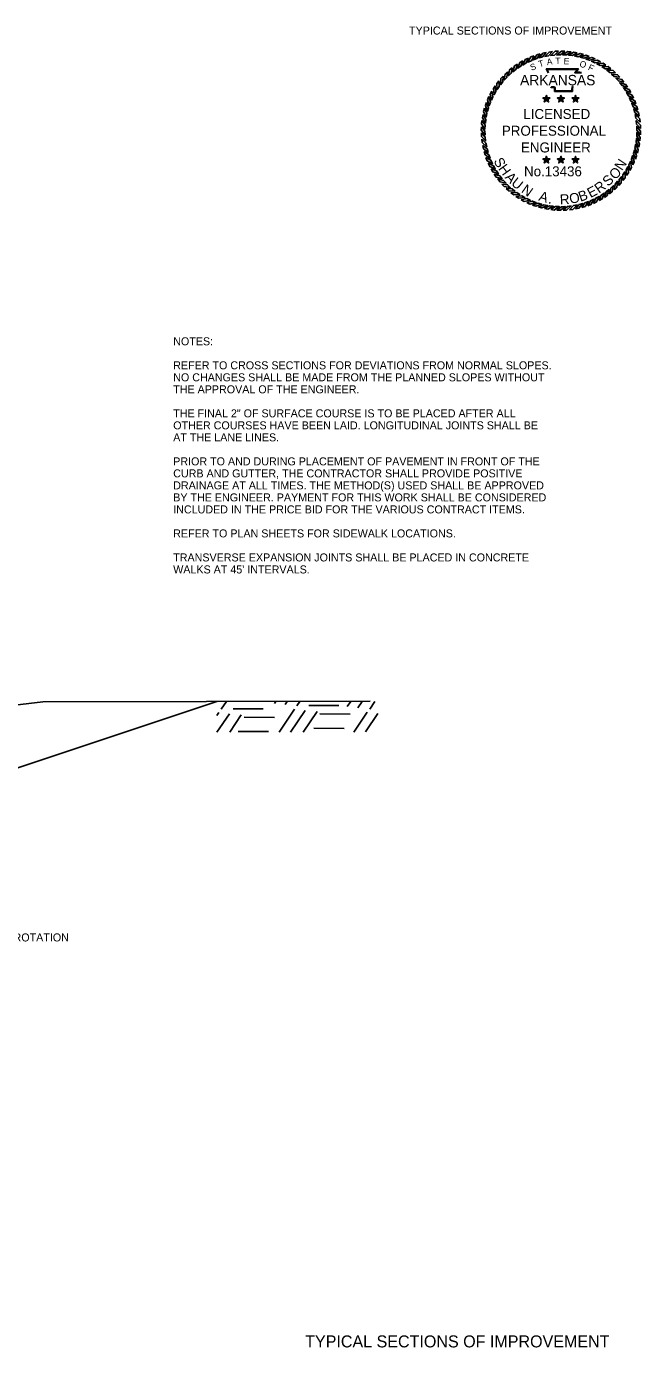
# Model space of a CAD drawing. Extents: x 1001270 to 1003428, y 1840152 to 1842912.
# Drawn here: x 1001382.5 to 1001428.5, y 1842659.1 to 1842758.1 of the extents above; entities that cross this region are included whole.
import ezdxf

# ---------------------------------------------------------------- set-up
doc = ezdxf.new("R2010")
doc.units = 0
for name, color, linetype in [('1', 7, 'Continuous'), ('19', 7, 'Continuous'), ('60', 7, 'Continuous'), ('G-ANNO-SYMB', 7, 'Continuous')]:
    doc.layers.add(name, color=color, linetype=linetype)

msp = doc.modelspace()

# ---------------------------------------------------------------- linework, layer by layer
at = {"layer": '19'}
for p, q in [((1001374.66, 1842700.132), (1001396.746, 1842707.494)), ((1001397.064, 1842706.913), (1001397.455, 1842707.495)), ((1001397.952, 1842706.952), (1001400.212, 1842706.93)), ((1001401.049, 1842707.347), (1001401.155, 1842707.497)), ((1001401.401, 1842705.2), (1001402.553, 1842706.921)), ((1001401.844, 1842707.255), (1001402.01, 1842707.499)), ((1001402.256, 1842705.202), (1001403.348, 1842706.829)), ((1001402.739, 1842707.163), (1001402.965, 1842707.502)), ((1001403.627, 1842707.192), (1001405.888, 1842707.181)), ((1001406.503, 1842707.107), (1001406.765, 1842707.502)), ((1001407.298, 1842707.015), (1001407.63, 1842707.504)), ((1001408.193, 1842706.923), (1001408.574, 1842707.497)), ((1001396.724, 1842706.445), (1001396.878, 1842706.67)), ((1001396.746, 1842705.196), (1001397.673, 1842706.578)), ((1001397.702, 1842705.198), (1001398.568, 1842706.486)), ((1001398.792, 1842706.322), (1001401.052, 1842706.301)), ((1001403.211, 1842705.204), (1001404.243, 1842706.737)), ((1001404.457, 1842706.564), (1001406.728, 1842706.551)), ((1001407.011, 1842705.205), (1001408.008, 1842706.681)), ((1001407.866, 1842705.208), (1001408.802, 1842706.589)), ((1001398.34, 1842705.243), (1001400.61, 1842705.231)), ((1001404.015, 1842705.493), (1001406.275, 1842705.472))]:
    msp.add_line(p, q, dxfattribs=at)
for points in [[(1001303.53, 1842696.307), (1001314.536, 1842695.921), (1001319.13, 1842696.006), (1001322.097, 1842696.031), (1001329.443, 1842696.396), (1001339.767, 1842697.462), (1001355.933, 1842698.662), (1001361.755, 1842701.104), (1001365.939, 1842701.981), (1001371.785, 1842704.915), (1001376.097, 1842706.564), (1001383.698, 1842707.466)], [(1001383.698, 1842707.466), (1001408.216, 1842707.519)]]:
    msp.add_lwpolyline(points, dxfattribs=at)
at = {"layer": 'G-ANNO-SYMB'}
for points in [[(1001419.658, 1842755.512), (1001419.436, 1842755.385), (1001419.276, 1842754.956), (1001419.507, 1842755.108)], [(1001420.078, 1842755.72), (1001419.846, 1842755.611), (1001419.653, 1842755.196), (1001419.896, 1842755.33)], [(1001420.513, 1842755.895), (1001420.273, 1842755.804), (1001420.048, 1842755.406), (1001420.3, 1842755.52)], [(1001420.96, 1842756.035), (1001420.714, 1842755.963), (1001420.458, 1842755.584), (1001420.719, 1842755.678)], [(1001421.416, 1842756.14), (1001421.165, 1842756.087), (1001420.881, 1842755.729), (1001421.148, 1842755.802)], [(1001421.88, 1842756.208), (1001421.625, 1842756.175), (1001421.314, 1842755.841), (1001421.586, 1842755.893)], [(1001422.347, 1842756.24), (1001422.091, 1842756.227), (1001421.754, 1842755.918), (1001422.029, 1842755.948)], [(1001422.816, 1842756.235), (1001422.559, 1842756.242), (1001422.199, 1842755.96), (1001422.476, 1842755.969)], [(1001423.282, 1842756.193), (1001423.027, 1842756.22), (1001422.646, 1842755.968), (1001422.923, 1842755.955)], [(1001423.744, 1842756.115), (1001423.492, 1842756.162), (1001423.092, 1842755.94), (1001423.367, 1842755.906)], [(1001424.198, 1842756), (1001423.951, 1842756.067), (1001423.535, 1842755.878), (1001423.806, 1842755.822)], [(1001424.642, 1842755.851), (1001424.401, 1842755.937), (1001423.971, 1842755.781), (1001424.237, 1842755.704)], [(1001425.073, 1842755.667), (1001424.839, 1842755.772), (1001424.398, 1842755.65), (1001424.658, 1842755.552)], [(1001425.488, 1842755.45), (1001425.263, 1842755.573), (1001424.814, 1842755.486), (1001425.065, 1842755.368)], [(1001425.885, 1842755.201), (1001425.67, 1842755.341), (1001425.216, 1842755.289), (1001425.457, 1842755.152)], [(1001418.18, 1842754.372), (1001418.008, 1842754.182), (1001417.988, 1842753.725), (1001418.161, 1842753.942)], [(1001418.515, 1842754.7), (1001418.329, 1842754.524), (1001418.273, 1842754.07), (1001418.462, 1842754.272)], [(1001418.874, 1842755.001), (1001418.675, 1842754.84), (1001418.584, 1842754.391), (1001418.789, 1842754.578)], [(1001419.256, 1842755.272), (1001419.045, 1842755.127), (1001418.919, 1842754.687), (1001419.138, 1842754.857)], [(1001426.261, 1842754.922), (1001426.058, 1842755.078), (1001425.601, 1842755.062), (1001425.83, 1842754.907)], [(1001426.614, 1842754.614), (1001426.424, 1842754.786), (1001425.967, 1842754.806), (1001426.183, 1842754.632)], [(1001426.942, 1842754.279), (1001426.765, 1842754.465), (1001426.312, 1842754.521), (1001426.514, 1842754.331)], [(1001417.593, 1842753.643), (1001417.453, 1842753.429), (1001417.504, 1842752.974), (1001417.642, 1842753.215)], [(1001417.872, 1842754.02), (1001417.716, 1842753.816), (1001417.732, 1842753.359), (1001417.887, 1842753.589)], [(1001427.242, 1842753.919), (1001427.081, 1842754.119), (1001426.633, 1842754.21), (1001426.82, 1842754.005)], [(1001427.513, 1842753.537), (1001427.368, 1842753.749), (1001426.929, 1842753.875), (1001427.099, 1842753.656)], [(1001427.754, 1842753.135), (1001427.626, 1842753.358), (1001427.198, 1842753.518), (1001427.35, 1842753.286)], [(1001416.943, 1842752.401), (1001416.857, 1842752.159), (1001417.013, 1842751.729), (1001417.09, 1842751.996)], [(1001417.127, 1842752.832), (1001417.022, 1842752.597), (1001417.144, 1842752.157), (1001417.242, 1842752.416)], [(1001417.344, 1842753.247), (1001417.221, 1842753.022), (1001417.308, 1842752.573), (1001417.426, 1842752.823)], [(1001421.427, 1842752.652), (1001421.366, 1842752.736), (1001421.167, 1842752.736), (1001421.328, 1842752.62)], [(1001421.427, 1842752.652), (1001421.328, 1842752.62), (1001421.266, 1842752.431), (1001421.427, 1842752.548)], [(1001421.427, 1842752.652), (1001421.488, 1842752.736), (1001421.427, 1842752.925), (1001421.366, 1842752.736)], [(1001421.427, 1842752.652), (1001421.526, 1842752.62), (1001421.686, 1842752.736), (1001421.488, 1842752.736)], [(1001421.427, 1842752.652), (1001421.427, 1842752.548), (1001421.587, 1842752.431), (1001421.526, 1842752.62)], [(1001422.518, 1842752.652), (1001422.456, 1842752.736), (1001422.258, 1842752.736), (1001422.419, 1842752.62)], [(1001422.518, 1842752.652), (1001422.419, 1842752.62), (1001422.357, 1842752.431), (1001422.518, 1842752.548)], [(1001422.518, 1842752.652), (1001422.579, 1842752.736), (1001422.518, 1842752.925), (1001422.456, 1842752.736)], [(1001422.518, 1842752.652), (1001422.617, 1842752.62), (1001422.777, 1842752.736), (1001422.579, 1842752.736)], [(1001422.518, 1842752.652), (1001422.518, 1842752.548), (1001422.678, 1842752.431), (1001422.617, 1842752.62)], [(1001423.609, 1842752.652), (1001423.547, 1842752.736), (1001423.349, 1842752.736), (1001423.51, 1842752.62)], [(1001423.609, 1842752.652), (1001423.51, 1842752.62), (1001423.448, 1842752.431), (1001423.609, 1842752.548)], [(1001423.609, 1842752.652), (1001423.67, 1842752.736), (1001423.609, 1842752.925), (1001423.547, 1842752.736)], [(1001423.609, 1842752.652), (1001423.708, 1842752.62), (1001423.868, 1842752.736), (1001423.67, 1842752.736)], [(1001423.609, 1842752.652), (1001423.609, 1842752.548), (1001423.769, 1842752.431), (1001423.708, 1842752.62)], [(1001427.962, 1842752.716), (1001427.852, 1842752.948), (1001427.438, 1842753.141), (1001427.571, 1842752.898)], [(1001428.137, 1842752.281), (1001428.045, 1842752.521), (1001427.647, 1842752.746), (1001427.761, 1842752.493)], [(1001416.679, 1842751.503), (1001416.632, 1842751.25), (1001416.854, 1842750.85), (1001416.888, 1842751.125)], [(1001416.793, 1842751.957), (1001416.726, 1842751.709), (1001416.916, 1842751.293), (1001416.972, 1842751.565)], [(1001428.277, 1842751.834), (1001428.204, 1842752.08), (1001427.825, 1842752.336), (1001427.919, 1842752.075)], [(1001428.381, 1842751.377), (1001428.328, 1842751.629), (1001427.97, 1842751.913), (1001428.044, 1842751.646)], [(1001428.449, 1842750.914), (1001428.417, 1842751.168), (1001428.082, 1842751.48), (1001428.134, 1842751.208)], [(1001416.559, 1842750.574), (1001416.552, 1842750.318), (1001416.833, 1842749.957), (1001416.825, 1842750.234)], [(1001416.601, 1842751.041), (1001416.574, 1842750.786), (1001416.826, 1842750.404), (1001416.839, 1842750.681)], [(1001428.481, 1842750.447), (1001428.468, 1842750.703), (1001428.159, 1842751.04), (1001428.19, 1842750.765)], [(1001428.476, 1842749.978), (1001428.483, 1842750.235), (1001428.202, 1842750.595), (1001428.211, 1842750.318)], [(1001416.554, 1842750.106), (1001416.567, 1842749.849), (1001416.876, 1842749.512), (1001416.845, 1842749.788)], [(1001416.586, 1842749.638), (1001416.619, 1842749.384), (1001416.953, 1842749.072), (1001416.901, 1842749.344)], [(1001428.356, 1842749.05), (1001428.404, 1842749.302), (1001428.182, 1842749.702), (1001428.147, 1842749.427)], [(1001428.434, 1842749.512), (1001428.462, 1842749.767), (1001428.209, 1842750.148), (1001428.196, 1842749.871)], [(1001416.654, 1842749.175), (1001416.707, 1842748.924), (1001417.065, 1842748.639), (1001416.992, 1842748.906)], [(1001416.759, 1842748.718), (1001416.831, 1842748.472), (1001417.21, 1842748.216), (1001417.116, 1842748.477)], [(1001428.092, 1842748.152), (1001428.179, 1842748.393), (1001428.022, 1842748.823), (1001427.945, 1842748.557)], [(1001428.242, 1842748.596), (1001428.309, 1842748.843), (1001428.119, 1842749.259), (1001428.063, 1842748.988)], [(1001416.899, 1842748.271), (1001416.99, 1842748.031), (1001417.388, 1842747.806), (1001417.274, 1842748.059)], [(1001417.073, 1842747.837), (1001417.183, 1842747.605), (1001417.598, 1842747.411), (1001417.464, 1842747.654)], [(1001417.282, 1842747.417), (1001417.409, 1842747.194), (1001417.838, 1842747.034), (1001417.685, 1842747.266)], [(1001421.427, 1842748.084), (1001421.366, 1842748.168), (1001421.167, 1842748.168), (1001421.328, 1842748.051)], [(1001421.427, 1842748.084), (1001421.328, 1842748.051), (1001421.266, 1842747.863), (1001421.427, 1842747.979)], [(1001421.427, 1842748.084), (1001421.488, 1842748.168), (1001421.427, 1842748.356), (1001421.366, 1842748.168)], [(1001421.427, 1842748.084), (1001421.526, 1842748.051), (1001421.686, 1842748.168), (1001421.488, 1842748.168)], [(1001421.427, 1842748.084), (1001421.427, 1842747.979), (1001421.587, 1842747.863), (1001421.526, 1842748.051)], [(1001422.518, 1842748.084), (1001422.456, 1842748.168), (1001422.258, 1842748.168), (1001422.419, 1842748.051)], [(1001422.518, 1842748.084), (1001422.419, 1842748.051), (1001422.357, 1842747.863), (1001422.518, 1842747.979)], [(1001422.518, 1842748.084), (1001422.579, 1842748.168), (1001422.518, 1842748.356), (1001422.456, 1842748.168)], [(1001422.518, 1842748.084), (1001422.617, 1842748.051), (1001422.777, 1842748.168), (1001422.579, 1842748.168)], [(1001422.518, 1842748.084), (1001422.518, 1842747.979), (1001422.678, 1842747.863), (1001422.617, 1842748.051)], [(1001423.609, 1842748.084), (1001423.547, 1842748.168), (1001423.349, 1842748.168), (1001423.51, 1842748.051)], [(1001423.609, 1842748.084), (1001423.51, 1842748.051), (1001423.448, 1842747.863), (1001423.609, 1842747.979)], [(1001423.609, 1842748.084), (1001423.67, 1842748.168), (1001423.609, 1842748.356), (1001423.547, 1842748.168)], [(1001423.609, 1842748.084), (1001423.708, 1842748.051), (1001423.868, 1842748.168), (1001423.67, 1842748.168)], [(1001423.609, 1842748.084), (1001423.609, 1842747.979), (1001423.769, 1842747.863), (1001423.708, 1842748.051)], [(1001427.442, 1842746.909), (1001427.583, 1842747.124), (1001427.531, 1842747.578), (1001427.394, 1842747.337)], [(1001427.691, 1842747.306), (1001427.814, 1842747.531), (1001427.727, 1842747.98), (1001427.609, 1842747.729)], [(1001427.909, 1842747.721), (1001428.013, 1842747.955), (1001427.891, 1842748.395), (1001427.793, 1842748.136)], [(1001417.522, 1842747.015), (1001417.667, 1842746.803), (1001418.106, 1842746.677), (1001417.936, 1842746.896)], [(1001417.793, 1842746.633), (1001417.954, 1842746.433), (1001418.402, 1842746.342), (1001418.216, 1842746.547)], [(1001426.52, 1842745.852), (1001426.707, 1842746.028), (1001426.763, 1842746.482), (1001426.573, 1842746.28)], [(1001426.855, 1842746.18), (1001427.027, 1842746.37), (1001427.047, 1842746.827), (1001426.874, 1842746.611)], [(1001427.163, 1842746.533), (1001427.32, 1842746.736), (1001427.304, 1842747.193), (1001427.148, 1842746.964)], [(1001418.094, 1842746.274), (1001418.27, 1842746.087), (1001418.724, 1842746.031), (1001418.522, 1842746.221)], [(1001418.421, 1842745.939), (1001418.612, 1842745.767), (1001419.069, 1842745.747), (1001418.852, 1842745.92)], [(1001418.774, 1842745.631), (1001418.978, 1842745.474), (1001419.435, 1842745.49), (1001419.205, 1842745.646)], [(1001425.377, 1842745.04), (1001425.599, 1842745.168), (1001425.76, 1842745.596), (1001425.528, 1842745.444)], [(1001425.779, 1842745.281), (1001425.991, 1842745.425), (1001426.117, 1842745.865), (1001425.898, 1842745.695)], [(1001426.161, 1842745.552), (1001426.361, 1842745.713), (1001426.452, 1842746.161), (1001426.247, 1842745.974)], [(1001419.15, 1842745.351), (1001419.365, 1842745.211), (1001419.82, 1842745.263), (1001419.579, 1842745.4)], [(1001419.547, 1842745.102), (1001419.772, 1842744.979), (1001420.221, 1842745.067), (1001419.97, 1842745.185)], [(1001419.962, 1842744.885), (1001420.196, 1842744.78), (1001420.637, 1842744.903), (1001420.378, 1842745)], [(1001420.393, 1842744.701), (1001420.635, 1842744.615), (1001421.064, 1842744.772), (1001420.798, 1842744.849)], [(1001420.837, 1842744.552), (1001421.085, 1842744.485), (1001421.501, 1842744.675), (1001421.229, 1842744.731)], [(1001421.291, 1842744.438), (1001421.543, 1842744.39), (1001421.943, 1842744.612), (1001421.668, 1842744.647)], [(1001421.753, 1842744.359), (1001422.008, 1842744.332), (1001422.39, 1842744.584), (1001422.113, 1842744.597)], [(1001422.22, 1842744.318), (1001422.476, 1842744.31), (1001422.837, 1842744.592), (1001422.56, 1842744.583)], [(1001422.688, 1842744.313), (1001422.944, 1842744.326), (1001423.282, 1842744.634), (1001423.006, 1842744.604)], [(1001423.156, 1842744.344), (1001423.41, 1842744.377), (1001423.722, 1842744.712), (1001423.45, 1842744.66)], [(1001423.619, 1842744.413), (1001423.87, 1842744.466), (1001424.155, 1842744.823), (1001423.887, 1842744.75)], [(1001424.076, 1842744.517), (1001424.322, 1842744.59), (1001424.577, 1842744.969), (1001424.317, 1842744.875)], [(1001424.523, 1842744.657), (1001424.762, 1842744.749), (1001424.988, 1842745.147), (1001424.735, 1842745.032)], [(1001424.957, 1842744.832), (1001425.189, 1842744.942), (1001425.382, 1842745.356), (1001425.14, 1842745.223)]]:
    msp.add_lwpolyline(points, close=True, dxfattribs=at)
for points in [[(1001421.562, 1842754.606), (1001421.423, 1842754.907), (1001423.829, 1842754.909), (1001423.628, 1842754.656), (1001423.792, 1842754.658), (1001423.928, 1842754.66), (1001424.065, 1842754.645)], [(1001421.596, 1842754.622), (1001421.482, 1842754.869), (1001423.75, 1842754.871), (1001423.548, 1842754.617), (1001423.792, 1842754.62), (1001423.926, 1842754.622), (1001424.06, 1842754.607)], [(1001423.45, 1842753.598), (1001423.409, 1842753.564), (1001423.395, 1842753.514), (1001423.382, 1842753.39), (1001423.382, 1842753.223), (1001422.038, 1842753.223), (1001422.038, 1842753.448), (1001422.038, 1842753.498), (1001421.984, 1842753.514), (1001421.793, 1842753.514), (1001421.759, 1842753.566)], [(1001423.426, 1842753.627), (1001423.375, 1842753.586), (1001423.358, 1842753.522), (1001423.344, 1842753.392), (1001423.344, 1842753.261), (1001422.077, 1842753.261), (1001422.077, 1842753.448), (1001422.077, 1842753.526), (1001421.99, 1842753.553), (1001421.813, 1842753.553), (1001421.791, 1842753.587)]]:
    msp.add_lwpolyline(points, dxfattribs=at)

# ---------------------------------------------------------------- texts
at = {"layer": '1'}
msp.add_text('TYPICAL SECTIONS OF IMPROVEMENT', height=0.6, dxfattribs=at).set_placement((1001411.138, 1842757.485))
at = {"layer": '19'}
for s, p in [('NOTES:', (1001393.468, 1842734.191)), ('REFER TO CROSS SECTIONS FOR DEVIATIONS FROM NORMAL SLOPES.', (1001393.468, 1842732.391)), ('NO CHANGES SHALL BE MADE FROM THE PLANNED SLOPES WITHOUT', (1001393.468, 1842731.491)), ('THE APPROVAL OF THE ENGINEER.', (1001393.468, 1842730.591)), ('THE FINAL 2" OF SURFACE COURSE IS TO BE PLACED AFTER ALL', (1001393.468, 1842728.791)), ('OTHER COURSES HAVE BEEN LAID. LONGITUDINAL JOINTS SHALL BE', (1001393.468, 1842727.891)), ('AT THE LANE LINES.', (1001393.468, 1842726.991)), ('PRIOR TO AND DURING PLACEMENT OF PAVEMENT IN FRONT OF THE', (1001393.468, 1842725.191)), ('CURB AND GUTTER, THE CONTRACTOR SHALL PROVIDE POSITIVE', (1001393.468, 1842724.291)), ('DRAINAGE AT ALL TIMES. THE METHOD(S) USED SHALL BE APPROVED', (1001393.468, 1842723.391)), ('BY THE ENGINEER. PAYMENT FOR THIS WORK SHALL BE CONSIDERED', (1001393.468, 1842722.491)), ('INCLUDED IN THE PRICE BID FOR THE VARIOUS CONTRACT ITEMS.', (1001393.468, 1842721.591)), ('REFER TO PLAN SHEETS FOR SIDEWALK LOCATIONS.', (1001393.468, 1842719.791)), ("WALKS AT 45' INTERVALS.", (1001393.468, 1842717.091)), ('TRANSVERSE EXPANSION JOINTS SHALL BE PLACED IN CONCRETE', (1001393.468, 1842717.991))]:
    msp.add_text(s, height=0.6, dxfattribs=at).set_placement(p)
msp.add_text('POINT OF SUPERELEVATION ROTATION', height=0.6, rotation=359.99538, dxfattribs=at).set_placement((1001370.005, 1842689.508))
at = {"layer": '60'}
msp.add_text('TYPICAL SECTIONS OF IMPROVEMENT', height=0.9, dxfattribs=at).set_placement((1001403.354, 1842659.077))
at = {"layer": 'G-ANNO-SYMB'}
for s, height, rotation, p in [('T', 0.475, 16.90148, (1001420.912, 1842755.035)), ('A', 0.475, 8.67877, (1001421.489, 1842755.185)), ('T', 0.475, 1.47887, (1001422.102, 1842755.28)), ('E', 0.475, 356.67203, (1001422.709, 1842755.266)), ('O', 0.475, 341.2218, (1001423.862, 1842755.103)), ('ARKANSAS', 0.7747, 360, (1001419.456, 1842753.684)), ('S', 0.475, 19.77256, (1001420.309, 1842754.764)), ('F', 0.475, 335.36282, (1001424.501, 1842754.853)), ('LICENSED', 0.75, 360, (1001419.696, 1842751.155)), ('PROFESSIONAL', 0.75, 360, (1001418.089, 1842749.901)), ('ENGINEER', 0.75, 360, (1001419.518, 1842748.647)), ('S', 0.75, 298.16364, (1001417.45, 1842748.016)), ('H', 0.75, 305.61905, (1001417.792, 1842747.429)), ('No.13436', 0.747, 360, (1001419.754, 1842746.859)), ('O', 0.75, 44.77573, (1001426.571, 1842746.557)), ('N', 0.75, 56.10067, (1001427.092, 1842747.233)), ('A', 0.75, 313.44722, (1001418.268, 1842746.744)), ('U', 0.75, 320.90262, (1001418.735, 1842746.255)), ('R', 0.75, 35.65967, (1001425.366, 1842745.55)), ('S', 0.75, 43.48784, (1001426.055, 1842746.06)), ('N', 0.75, 324.93262, (1001419.491, 1842745.696)), ('A', 0.75, 343.09908, (1001420.799, 1842745.053)), ('R', 0.75, 3.22866, (1001422.455, 1842744.739)), ('O', 0.75, 11.42961, (1001423.223, 1842744.788)), ('B', 0.75, 18.88501, (1001423.974, 1842744.947)), ('E', 0.75, 27.83149, (1001424.732, 1842745.218)), ('.', 0.75, 351.30002, (1001421.536, 1842744.834))]:
    msp.add_text(s, height=height, rotation=rotation, dxfattribs=at).set_placement(p)

doc.saveas('drawing.dxf')
